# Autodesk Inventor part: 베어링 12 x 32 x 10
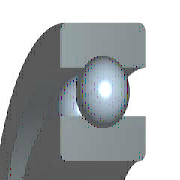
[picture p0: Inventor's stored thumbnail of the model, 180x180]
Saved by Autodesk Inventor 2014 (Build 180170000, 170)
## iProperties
IsCustomPart: 1
Created: 2012-02
Part Number: 베어링 12 x 32 x 10
Material: 강철, 연강
Description: 깊은 그루브 볼 베어링
Document SubType Name: Modeling
Standard: KS B 2023
Designer: test
Standards Organization: KS
Language: ko-KR
Size Designation: 6201 - 12 x 32 x 10
Categories: <MemberInstance><Categories><Category DisplayName="샤프트 부품" InternalName="7f7aeb1f-a693-4053-b835-cee3144e0d98" Mnemonic="SHFT"><Category DisplayName="베어링" Inter
Density: 1 g/cm^3
Appearance: 노란색
Author: test
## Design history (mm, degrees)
sketch "스케치" dims "d0" = 5.2 (= -0.26 x WD + 0.26 x BD)
  geometry: L1 (2.4, 11)-(7.6, 11); L2 (5, 11)-(5, 8.4); L3 (5, 11)-(5, 13.6); L4 (3.068, 9.26)-(0, 9.26); L5 (0, 6)-(10, 6); L6 (3.068, 12.74)-(0, 12.74); L7 (0, 16)-(10, 16); L8 (10, 6)-(10, 9.26); L9 (6.932, 9.26)-(10, 9.26); L10 (6.932, 12.74)-(10, 12.74); L11 (10, 16)-(10, 12.74); L12 (-1.4, 0)-(8.4, 0) reference; L13 (0, -0.3)-(0, 5.3) reference
  constraints: 22 end point, 4 point on line, 2 collinear, 2 perpendicular, 2 symmetric about line, 1 midpoint, 1 parallel, 14 other
  dimensions: "d9" = 12 diameter of L5 L12 (= WD); "d11" = 32 diameter of L7 L12 (= BD); "d12" = 10 distance between parallel lines of L8 L13 (= KB); "d13" = 18.52 diameter of L9 L12 (= 0.326 x BD + 0.674 x WD)
revolve "본체" stored, may be unused: angle "d6" = 90 deg
revolve "볼" stored, may be unused: angle "d7" = 90 deg
pattern_circular "IDS_ARRAYBALL[SIMPL:T]" dims angle "d3" = 360 deg
body "Solid1"
fillet "모깎기1" dims "d1" = 0.6 (= KRS)
other parameters: "WD" = 12 [user parameter; used in 5 equation terms], "BD" = 32 [user parameter; used in 5 equation terms], "KB" = 10 [user parameter; used in 1 equation term], "KRS" = 0.6 [user parameter; used in 1 equation term], "d4" = 0, "d5" = 0, "d8" = 0, "d14" = 0, "d15" = 0, "BBA" = 0 [user parameter], "BC0" = 3100000 [user parameter], "BC" = 6890000 [user parameter], "BR" = 16 (= 0.5 x BD) [user parameter], "WR" = 6 (= 0.5 x WD) [user parameter]
